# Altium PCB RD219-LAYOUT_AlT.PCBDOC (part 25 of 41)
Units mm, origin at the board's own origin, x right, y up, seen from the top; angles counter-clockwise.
Board outline 209.75 x 159.97 mm, 2 copper layers (TOP, BOTTOM), stack 0 mm thick; 398 components, 199 nets, 1469 pads, 0 vias.
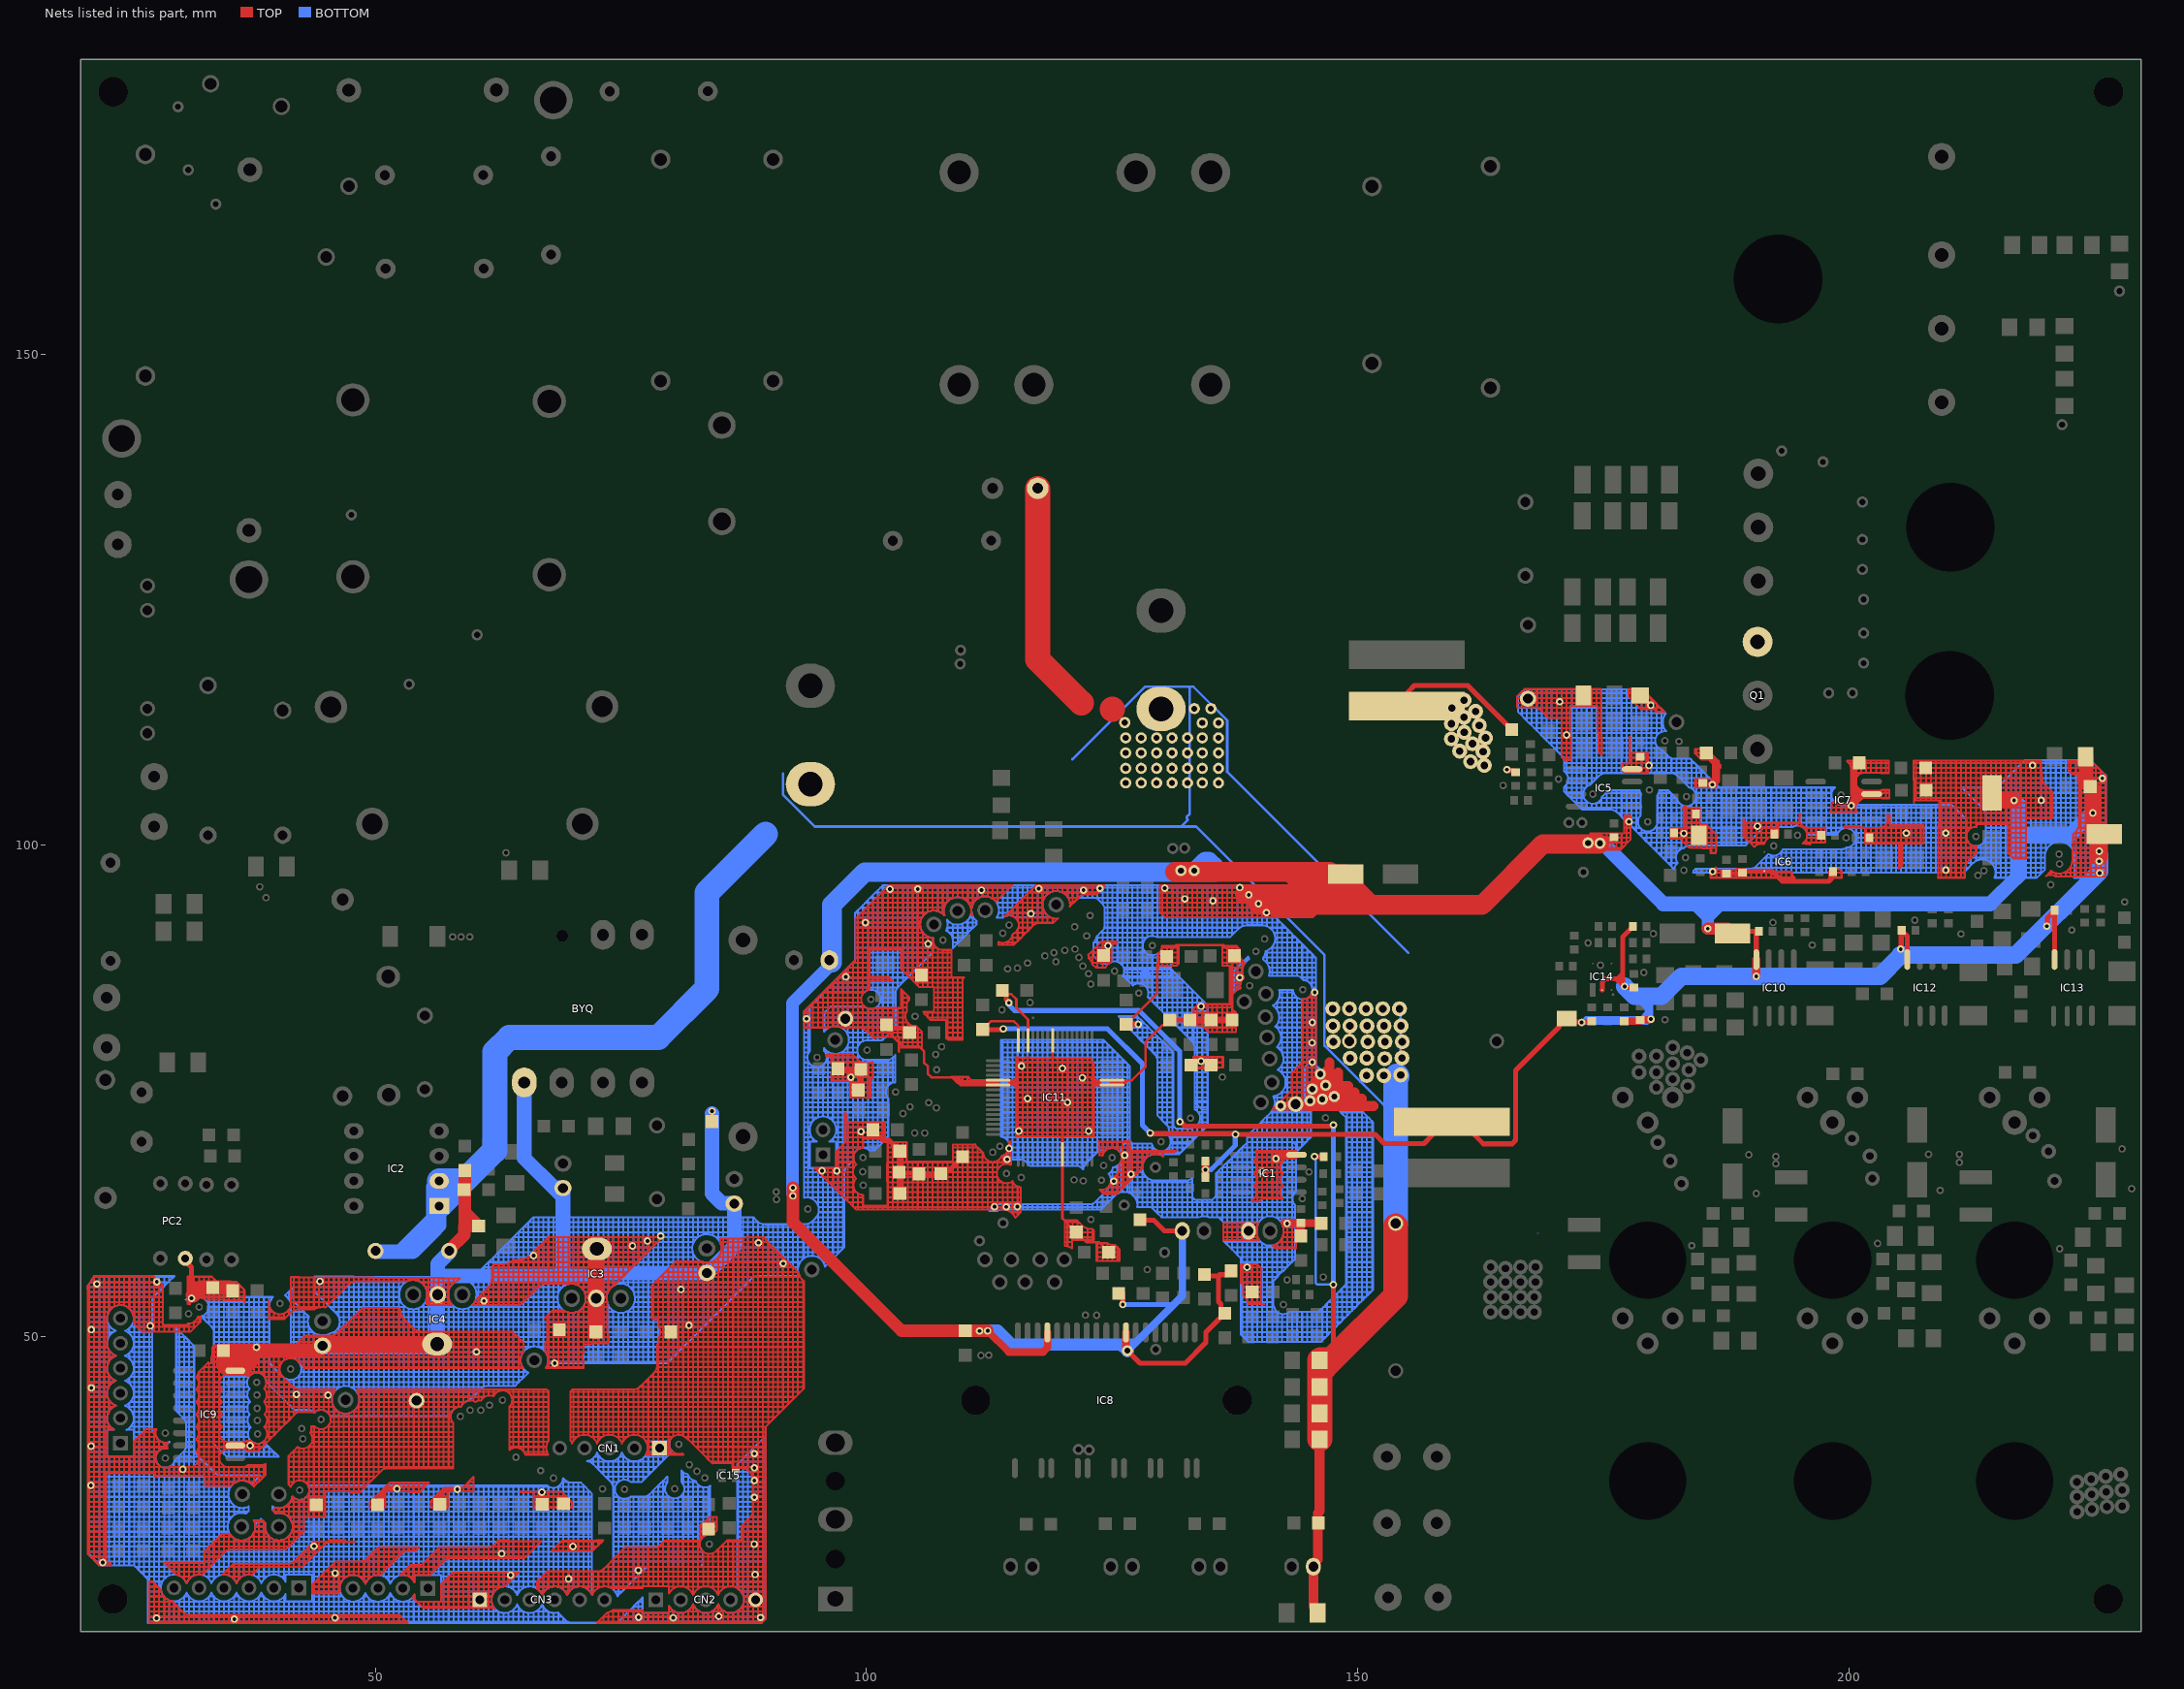
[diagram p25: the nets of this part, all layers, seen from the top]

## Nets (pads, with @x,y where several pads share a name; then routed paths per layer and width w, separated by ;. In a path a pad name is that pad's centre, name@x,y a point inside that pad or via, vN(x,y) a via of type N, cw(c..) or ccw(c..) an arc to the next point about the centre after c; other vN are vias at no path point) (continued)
GND: (continued)
  BOTTOM w0.203: 58.989,20.889 58.989,21.016 ; 58.989,20.889 59.497,20.889 ; 58.989,21.016 58.989,21.524 ; 58.989,21.016 59.497,21.016 ; 58.989,21.524 58.989,22.032 ; 58.989,21.524 59.497,21.524 ; 58.989,22.032 58.989,22.54 ; 58.989,22.032 59.497,22.032 ; 58.989,22.54 58.989,23.048 ; 58.989,22.54 59.497,22.54 ; 58.989,23.048 58.989,23.556 ; 58.989,23.048 59.497,23.048 ; 58.989,23.556 58.989,24.064 ; 58.989,23.556 59.497,23.556 ; 58.989,24.064 58.989,24.572 ; 58.989,24.064 59.497,24.064 ; 58.989,24.572 58.989,25.08 ; 58.989,24.572 59.497,24.572 ; 58.989,25.08 58.989,25.588 ; 58.989,25.08 59.497,25.08 ; 58.989,25.588 58.989,26.096 ; 58.989,25.588 59.497,25.588 ; 58.989,26.096 58.989,26.604 ; 58.989,26.096 59.497,26.096 ; 58.989,26.604 58.989,27.112 ; 58.989,26.604 59.497,26.604 ; 58.989,27.112 58.989,27.62 ; 58.989,27.112 59.497,27.112 ; 58.989,27.62 58.989,28.128 ; 58.989,27.62 59.497,27.62 ; 58.989,28.128 58.989,28.636 ; 58.989,28.128 59.497,28.128 ; 58.989,28.636 58.989,29.144 ; 58.989,28.636 59.497,28.636 ; 58.989,29.144 58.989,29.652 ; 58.989,29.144 59.497,29.144 ; 58.989,29.652 58.989,30.16 ; 58.989,29.652 59.497,29.652 ; 58.989,30.16 58.989,30.668 ; 58.989,30.16 59.497,30.16 ; 58.989,30.668 58.989,31.176 ; 58.989,30.668 59.497,30.668 ; 58.989,31.176 58.989,31.684 ; 58.989,31.176 59.497,31.176 ; 58.989,31.684 58.989,32.192 ; 58.989,31.684 59.497,31.684 ; 58.989,32.192 58.989,32.7 ; 58.989,32.192 59.497,32.192 ; 58.989,32.7 58.989,33.208 ; 58.989,32.7 59.497,32.7 ; 58.989,33.208 58.989,33.716 ; 58.989,33.208 59.497,33.208 ; 58.989,33.716 58.989,34.224 ; 58.989,33.716 59.497,33.716 ; 58.989,34.224 58.989,34.732 ; 58.989,34.224 59.497,34.224 ; 58.989,34.732 58.989,34.866 ; 58.989,34.732 59.497,34.732 ; 58.989,34.866 59.497,34.866 ; 58.989,43.261 cw(c59.646,42.53) 59.133,43.368 ; 58.989,43.261 58.989,43.368 ; 58.989,43.368 58.989,43.876 ; 58.989,43.368 59.133,43.368 ; 58.989,43.876 58.989,44.384 ; 58.989,43.876 59.497,43.876 ; 58.989,44.384 59.497,44.384 ; 58.989,44.384 58.989,44.892 ; 58.989,44.892 59.497,44.892 ; 58.989,44.892 58.989,45.4 ; 58.989,45.4 59.497,45.4 ; 58.989,45.4 58.989,45.908 ; 58.989,45.908 58.989,46.416 ; 58.989,45.908 59.497,45.908 ; 58.989,46.416 59.497,46.416 ; 58.989,46.416 58.989,46.924 ; 58.989,46.924 58.989,47.432 ; 58.989,46.924 59.497,46.924 ; 58.989,47.432 59.497,47.432 ; 58.989,47.432 58.989,47.94 ; 58.989,47.94 58.989,48.448 ; 58.989,47.94 59.497,47.94 ; 58.989,48.448 58.989,48.956 ; 58.989,48.448 59.497,48.448 ; 58.989,48.956 58.989,49.464 ; 58.989,48.956 59.497,48.956 ; 58.989,49.464 58.989,49.972 ; 58.989,49.464 59.497,49.464 ; 58.989,49.972 58.989,50.48 ; 58.989,49.972 59.497,49.972 ; 58.989,50.48 58.989,50.988 ; 58.989,50.48 59.497,50.48 ; 58.989,50.988 59.497,50.988 ; 58.989,50.988 58.989,51.496 ; 58.989,51.496 59.497,51.496 ; 58.989,51.496 58.989,52.004 ; 58.989,52.004 58.989,52.512 ; 58.989,52.004 59.497,52.004 ; 58.989,52.512 59.497,52.512 ; 58.989,52.512 58.989,52.805 ; 58.989,52.805 ccw(c58.862,54.227) 59.497,52.948 ; 58.989,55.775 cw(c58.862,54.354) 59.497,55.632 ; 58.989,55.775 58.989,56.068 ; 58.989,56.068 58.989,56.071 ; 58.989,56.068 59.497,56.068 ; 58.989,56.071 59.497,56.07 ; 59.133,43.368 cw(c59.646,42.53) 59.497,43.501 ; 59.497,20.889 59.497,21.016 ; 59.497,20.889 60.005,20.889 ; 59.497,21.016 59.497,21.524 ; 59.497,21.016 60.005,21.016 ; 59.497,21.524 59.497,22.032 ; 59.497,21.524 60.005,21.524 ; 59.497,22.032 59.497,22.54 ; 59.497,22.032 60.005,22.032 ; 59.497,22.54 59.497,23.048 ; 59.497,22.54 CN3.1@60.005,22.54 ; 59.497,23.048 59.497,23.556 ; 59.497,23.048 CN3.1@60.005,23.048 ; 59.497,23.556 59.497,24.064 ; 59.497,23.556 CN3.1@60.005,23.556 ; 59.497,24.064 59.497,24.572 ; 59.497,24.064 60.005,24.064 ; 59.497,24.572 59.497,25.08 ; 59.497,24.572 60.005,24.572 ; 59.497,25.08 59.497,25.588 ; 59.497,25.08 60.005,25.08 ; 59.497,25.588 59.497,26.096 ; 59.497,25.588 60.005,25.588 ; 59.497,26.096 59.497,26.604 ; 59.497,26.096 60.005,26.096 ; 59.497,26.604 59.497,27.112 ; 59.497,26.604 60.005,26.604 ; 59.497,27.112 59.497,27.62 ; 59.497,27.112 60.005,27.112 ; 59.497,27.62 59.497,28.128 ; 59.497,27.62 60.005,27.62 ; 59.497,28.128 59.497,28.636 ; 59.497,28.128 60.005,28.128 ; 59.497,28.636 59.497,29.144 ; 59.497,28.636 60.005,28.636 ; 59.497,29.144 59.497,29.652 ; 59.497,29.144 60.005,29.144 ; 59.497,29.652 59.497,30.16 ; 59.497,29.652 60.005,29.652 ; 59.497,30.16 59.497,30.668 ; 59.497,30.16 60.005,30.16 ; 59.497,30.668 59.497,31.176 ; 59.497,30.668 60.005,30.668 ; 59.497,31.176 59.497,31.684 ; 59.497,31.176 60.005,31.176 ; 59.497,31.684 59.497,32.192 ; 59.497,31.684 60.005,31.684 ; 59.497,32.192 59.497,32.7 ; 59.497,32.192 60.005,32.192 ; 59.497,32.7 59.497,33.208 ; 59.497,32.7 60.005,32.7 ; 59.497,33.208 59.497,33.716 ; 59.497,33.208 60.005,33.208 ; 59.497,33.716 59.497,34.224 ; 59.497,33.716 60.005,33.716 ; 59.497,34.224 59.497,34.732 ; 59.497,34.224 60.005,34.224 ; 59.497,34.732 59.497,34.866 ; 59.497,34.732 60.005,34.732 ; 59.497,34.866 60.005,34.866 ; 59.497,43.501 59.497,43.876 ; 59.497,43.876 59.497,44.384 ; 59.497,43.876 59.962,43.876 ; 59.497,44.384 59.497,44.892 ; 59.497,44.384 60.005,44.384 ; 59.497,44.892 59.497,45.4 ; 59.497,44.892 60.005,44.892 ; 59.497,45.4 60.005,45.4 ; 59.497,45.4 59.497,45.908 ; 59.497,45.908 59.497,46.416 ; 59.497,45.908 60.005,45.908 ; 59.497,46.416 59.497,46.924 ; 59.497,46.416 60.005,46.416 ; 59.497,46.924 59.497,47.432 ; 59.497,46.924 60.005,46.924 ; 59.497,47.432 59.497,47.94 ; 59.497,47.432 60.005,47.432 ; 59.497,47.94 59.497,48.448 ; 59.497,47.94 60.005,47.94 ; 59.497,48.448 59.497,48.956 ; 59.497,48.448 pad.@60.005,48.448 ; 59.497,48.956 59.497,49.464 ; 59.497,48.956 60.005,48.956 ; 59.497,49.464 59.497,49.972 ; 59.497,49.464 60.005,49.464 ; 59.497,49.972 59.497,50.48 ; 59.497,49.972 60.005,49.972 ; 59.497,50.48 59.497,50.988 ; 59.497,50.48 60.005,50.48 ; 59.497,50.988 59.497,51.496 ; 59.497,50.988 60.005,50.988 ; 59.497,51.496 59.497,52.004 ; 59.497,51.496 60.005,51.496 ; 59.497,52.004 59.497,52.512 ; 59.497,52.004 60.005,52.004 ; 59.497,52.512 60.005,52.512 ; 59.497,52.512 59.497,52.948 ; 59.497,52.948 ccw(c58.862,54.227) 59.624,53.02 ; 59.497,55.632 cw(c58.862,54.354) 59.618,55.564 cw(c58.862,54.354) 59.624,55.56 ; 59.497,55.632 59.497,56.068 ; 59.497,56.068 60.005,56.068 ; 59.497,56.068 59.497,56.07 ; 59.497,56.07 60.005,56.068 ; 59.624,53.02 ccw(c58.862,54.227) 60.002,53.368 ccw(c58.862,54.227) 60.005,53.372 ; 59.624,53.02 60.005,53.02 ; 59.624,55.56 cw(c58.862,54.354) 60.005,55.208 ; 59.624,55.56 60.005,55.56 ; 59.962,43.876 60.005,43.919 ; 60.005,20.889 60.005,21.016 ; 60.005,20.889 60.513,20.889 ; 60.005,21.016 60.005,21.524 ; 60.005,21.016 60.513,21.016 ; 60.005,21.524 60.005,22.032 ; 60.005,21.524 60.513,21.524 ; 60.005,22.032 CN3.1@60.005,22.54 ; 60.005,22.032 60.513,22.032 ; CN3.1@60.005,22.54 CN3.1@60.005,23.048 ; CN3.1@60.005,22.54 CN3.1@60.513,22.54 ; CN3.1@60.005,23.048 CN3.1@60.513,23.048 ; CN3.1@60.005,23.048 CN3.1@60.005,23.556 ; CN3.1@60.005,23.556 60.005,24.064 ; CN3.1@60.005,23.556 CN3.1@60.513,23.556 ; 60.005,24.064 60.005,24.572 ; 60.005,24.064 60.513,24.064 ; 60.005,24.572 60.005,25.08 ; 60.005,24.572 60.513,24.572 ; 60.005,25.08 60.005,25.588 ; 60.005,25.08 60.513,25.08 ; 60.005,25.588 60.005,26.096 ; 60.005,25.588 60.513,25.588 ; 60.005,26.096 60.005,26.604 ; 60.005,26.096 60.513,26.096 ; 60.005,26.604 60.005,27.112 ; 60.005,26.604 60.513,26.604 ; 60.005,27.112 60.005,27.62 ; 60.005,27.112 60.513,27.112 ; 60.005,27.62 60.005,28.128 ; 60.005,27.62 60.513,27.62 ; 60.005,28.128 60.005,28.636 ; 60.005,28.128 60.513,28.128 ; 60.005,28.636 60.005,29.144 ; 60.005,28.636 60.513,28.636 ; 60.005,29.144 60.005,29.652 ; 60.005,29.144 60.513,29.144 ; 60.005,29.652 60.005,30.16 ; 60.005,29.652 60.513,29.652 ; 60.005,30.16 60.005,30.668 ; 60.005,30.16 60.513,30.16 ; 60.005,30.668 60.005,31.176 ; 60.005,30.668 60.513,30.668 ; 60.005,31.176 60.005,31.684 ; 60.005,31.176 60.513,31.176 ; 60.005,31.684 60.005,32.192 ; 60.005,31.684 60.513,31.684 ; 60.005,32.192 60.005,32.7 ; 60.005,32.192 60.513,32.192 ; 60.005,32.7 60.005,33.208 ; 60.005,32.7 60.513,32.7 ; 60.005,33.208 60.005,33.716 ; 60.005,33.208 60.513,33.208 ; 60.005,33.716 60.005,34.224 ; 60.005,33.716 60.513,33.716 ; 60.005,34.224 60.005,34.732 ; 60.005,34.224 60.513,34.224 ; 60.005,34.732 60.005,34.866 ; 60.005,34.732 60.513,34.732 ; 60.005,34.866 60.513,34.866 ; 60.005,43.919 60.47,44.384 ; 60.005,43.919 60.005,44.384 ; 60.005,44.384 60.47,44.384 ; 60.005,44.384 60.005,44.892 ; 60.005,44.892 60.513,44.892 ; 60.005,44.892 60.005,45.4 ; 60.005,45.4 60.513,45.4 ; 60.005,45.4 60.005,45.908 ; 60.005,45.908 60.005,46.416 ; 60.005,45.908 60.513,45.908 ; 60.005,46.416 60.513,46.416 ; 60.005,46.416 60.005,46.924 ; 60.005,46.924 60.005,47.432 ; 60.005,46.924 60.513,46.924 ; 60.005,47.432 60.513,47.432 ; 60.005,47.432 60.005,47.94 ; 60.005,47.94 pad.@60.005,48.448 ; 60.005,47.94 60.513,47.94 ; pad.@60.005,48.448 pad.@60.513,48.448 ; pad.@60.005,48.448 60.005,48.956 ; 60.005,48.956 60.005,49.464 ; 60.005,48.956 60.513,48.956 ; 60.005,49.464 60.005,49.972 ; 60.005,49.464 60.513,49.464 ; 60.005,49.972 60.005,50.48 ; 60.005,49.972 60.513,49.972 ; 60.005,50.48 60.005,50.988 ; 60.005,50.48 60.513,50.48 ; 60.005,50.988 60.513,50.988 ; 60.005,50.988 60.005,51.496 ; 60.005,51.496 60.513,51.496 ; 60.005,51.496 60.005,52.004 ; 60.005,52.004 60.005,52.512 ; 60.005,52.004 60.513,52.004 ; 60.005,52.512 60.005,53.02 ; 60.005,52.512 60.513,52.512 ; 60.005,53.02 60.513,53.02 ; 60.005,53.02 60.005,53.372 ; 60.005,53.372 ccw(c58.862,54.227) 60.106,53.528 ; 60.005,55.208 cw(c58.862,54.354) 60.106,55.052 ; 60.005,55.208 60.005,55.56 ; 60.005,55.56 60.005,56.068 ; 60.005,55.56 60.513,55.56 ; 60.005,56.068 60.132,56.195 60.513,56.576 ; 60.005,56.068 60.513,56.068 ; 60.106,53.528 ccw(c58.862,54.227) 60.276,54.036 ; 60.106,53.528 60.513,53.528 ; 60.106,55.052 cw(c58.862,54.354) 60.276,54.544 ; 60.106,55.052 60.513,55.052 ; 60.276,54.036 ccw(c58.862,54.227) 60.289,54.227 60.289,54.354 ccw(c58.862,54.354) 60.276,54.544 ; 60.276,54.036 60.513,54.036 ; 60.276,54.544 60.513,54.544 ; 60.47,44.384 60.513,44.427 ; 60.513,20.889 60.513,21.016 ; 60.513,20.889 61.021,20.889 ; 60.513,21.016 60.513,21.524 ; 60.513,21.016 61.021,21.016 ; 60.513,21.524 60.513,22.032 ; 60.513,21.524 61.021,21.524 ; 60.513,22.032 CN3.1@60.513,22.54 ; 60.513,22.032 61.021,22.032 ; CN3.1@60.513,22.54 CN3.1@60.513,23.048 ; CN3.1@60.513,22.54 CN3.1@61.021,22.54 ; CN3.1@60.513,23.048 CN3.1@61.021,23.048 ; CN3.1@60.513,23.048 CN3.1@60.513,23.556 ; CN3.1@60.513,23.556 60.513,24.064 ; CN3.1@60.513,23.556 CN3.1@61.021,23.556 ; 60.513,24.064 60.513,24.572 ; 60.513,24.064 61.021,24.064 ; 60.513,24.572 60.513,25.08 ; 60.513,24.572 61.021,24.572 ; 60.513,25.08 60.513,25.588 ; 60.513,25.08 61.021,25.08 ; 60.513,25.588 60.513,26.096 ; 60.513,25.588 61.021,25.588 ; 60.513,26.096 60.513,26.604 ; 60.513,26.096 61.021,26.096 ; 60.513,26.604 60.513,27.112 ; 60.513,26.604 61.021,26.604 ; 60.513,27.112 60.513,27.62 ; 60.513,27.112 61.021,27.112 ; 60.513,27.62 60.513,28.128 ; 60.513,27.62 61.021,27.62 ; 60.513,28.128 60.513,28.636 ; 60.513,28.128 61.021,28.128 ; 60.513,28.636 60.513,29.144 ; 60.513,28.636 61.021,28.636 ; 60.513,29.144 60.513,29.652 ; 60.513,29.144 61.021,29.144 ; 60.513,29.652 60.513,30.16 ; 60.513,29.652 61.021,29.652 ; 60.513,30.16 60.513,30.668 ; 60.513,30.16 61.021,30.16 ; 60.513,30.668 60.513,31.176 ; 60.513,30.668 61.021,30.668 ; 60.513,31.176 60.513,31.684 ; 60.513,31.176 61.021,31.176 ; 60.513,31.684 60.513,32.192 ; 60.513,31.684 61.021,31.684 ; 60.513,32.192 60.513,32.7 ; 60.513,32.192 61.021,32.192 ; 60.513,32.7 60.513,33.208 ; 60.513,32.7 61.021,32.7 ; 60.513,33.208 60.513,33.716 ; 60.513,33.208 61.021,33.208 ; 60.513,33.716 60.513,34.224 ; 60.513,33.716 61.021,33.716 ; 60.513,34.224 60.513,34.732 ; 60.513,34.224 61.021,34.224 ; 60.513,34.732 60.513,34.866 ; 60.513,34.732 61.021,34.732 ; 60.513,34.866 61.021,34.866 ; 60.513,44.427 60.513,44.892 ; 60.513,44.427 60.858,44.772 ; 60.513,44.892 60.513,45.4 ; 60.513,44.892 61.016,44.892 ; 60.513,45.4 61.021,45.4 ; 60.513,45.4 60.513,45.908 ; 60.513,45.908 60.513,46.416 ; 60.513,45.908 61.021,45.908 ; 60.513,46.416 61.021,46.416 ; 60.513,46.416 60.513,46.924 ; 60.513,46.924 60.513,47.432 ; 60.513,46.924 61.021,46.924 ; 60.513,47.432 61.021,47.432 ; 60.513,47.432 60.513,47.94 ; 60.513,47.94 pad.@60.513,48.448 ; 60.513,47.94 61.021,47.94 ; pad.@60.513,48.448 61.021,48.448 ; pad.@60.513,48.448 60.513,48.956 ; 60.513,48.956 60.513,49.464 ; 60.513,48.956 61.021,48.956 ; 60.513,49.464 60.513,49.972 ; 60.513,49.464 61.021,49.464 ; 60.513,49.972 60.513,50.48 ; 60.513,49.972 61.021,49.972 ; 60.513,50.48 60.513,50.988 ; 60.513,50.48 61.021,50.48 ; 60.513,50.988 61.021,50.988 ; 60.513,50.988 60.513,51.496 ; 60.513,51.496 61.021,51.496 ; 60.513,51.496 60.513,52.004 ; 60.513,52.004 60.513,52.512 ; 60.513,52.004 61.021,52.004 ; 60.513,52.512 60.513,53.02 ; 60.513,52.512 61.021,52.512 ; 60.513,53.02 61.021,53.02 ; 60.513,53.02 60.513,53.528 ; 60.513,53.528 60.513,54.036 ; 60.513,53.528 pad.@61.021,53.528 ; 60.513,54.036 60.513,54.544 ; 60.513,54.036 61.021,54.036 ; 60.513,54.544 60.513,55.052 ; 60.513,54.544 61.021,54.544 ; 60.513,55.052 60.513,55.56 ; 60.513,55.052 61.021,55.052 ; 60.513,55.56 60.513,56.068 ; 60.513,55.56 61.021,55.56 ; 60.513,56.068 61.021,56.068 ; 60.513,56.068 60.513,56.195 60.513,56.576 ; 60.513,56.576 61.021,56.576 ; 60.513,56.576 61.021,57.084 ; 60.858,44.772 cw(c61.373,44.257) 61.016,44.892 ; 60.858,44.772 cw(c61.373,44.257) 61.016,44.892 ; 61.016,44.892 cw(c61.373,44.257) 61.021,44.895 ; 61.016,44.892 cw(c61.373,44.257) 61.021,44.895 ; 61.021,20.889 61.021,21.016 ; 61.021,20.889 61.529,20.889 ; 61.021,21.016 61.021,21.524 ; 61.021,21.016 61.529,21.016 ; 61.021,21.524 61.021,22.032 ; 61.021,21.524 61.529,21.524 ; 61.021,22.032 CN3.1@61.021,22.54 ; 61.021,22.032 61.529,22.032 ; CN3.1@61.021,22.54 CN3.1@61.021,23.048 ; CN3.1@61.021,22.54 61.529,22.54 ; CN3.1@61.021,23.048 61.529,23.048 ; CN3.1@61.021,23.048 CN3.1@61.021,23.556 ; CN3.1@61.021,23.556 61.021,24.064 ; CN3.1@61.021,23.556 61.529,23.556 ; 61.021,24.064 61.021,24.572 ; 61.021,24.064 61.529,24.064 ; 61.021,24.572 61.021,25.08 ; 61.021,24.572 61.529,24.572 ; 61.021,25.08 61.021,25.588 ; 61.021,25.08 61.529,25.08 ; 61.021,25.588 61.021,26.096 ; 61.021,25.588 61.529,25.588 ; 61.021,26.096 61.021,26.604 ; 61.021,26.096 61.529,26.096 ; 61.021,26.604 61.021,27.112 ; 61.021,26.604 61.529,26.604 ; 61.021,27.112 61.021,27.62 ; 61.021,27.112 61.529,27.112 ; 61.021,27.62 61.021,28.128 ; 61.021,27.62 61.529,27.62 ; 61.021,28.128 61.021,28.636 ; 61.021,28.128 61.529,28.128 ; 61.021,28.636 61.021,29.144 ; 61.021,28.636 61.529,28.636 ; 61.021,29.144 61.021,29.652 ; 61.021,29.144 61.529,29.144 ; 61.021,29.652 61.021,30.16 ; 61.021,29.652 61.529,29.652 ; 61.021,30.16 61.021,30.668 ; 61.021,30.16 61.529,30.16 ; 61.021,30.668 61.021,31.176 ; 61.021,30.668 61.529,30.668 ; 61.021,31.176 61.021,31.684 ; 61.021,31.176 61.529,31.176 ; 61.021,31.684 61.021,32.192 ; 61.021,31.684 61.529,31.684 ; 61.021,32.192 61.021,32.7 ; 61.021,32.192 61.529,32.192 ; 61.021,32.7 61.021,33.208 ; 61.021,32.7 61.529,32.7 ; 61.021,33.208 61.021,33.716 ; 61.021,33.208 61.529,33.208 ; 61.021,33.716 61.021,34.224 ; 61.021,33.716 61.529,33.716 ; 61.021,34.224 61.021,34.732 ; 61.021,34.224 61.529,34.224 ; 61.021,34.732 61.021,34.866 ; 61.021,34.732 61.529,34.732 ; 61.021,34.866 61.529,34.866 ; 61.021,44.895 cw(c61.373,44.257) 61.373,44.986 ; 61.021,44.895 cw(c61.373,44.257) 61.373,44.986 ; 61.021,44.895 61.021,45.4 ; 61.021,45.4 61.021,45.908 ; 61.021,45.4 61.529,45.4 ; 61.021,45.908 61.021,46.416 ; 61.021,45.908 61.529,45.908 ; 61.021,46.416 61.021,46.924 ; 61.021,46.416 61.529,46.416 ; 61.021,46.924 61.021,47.432 ; 61.021,46.924 61.529,46.924 ; 61.021,47.432 61.021,47.94 ; 61.021,47.432 61.529,47.432 ; 61.021,47.94 61.021,48.448 ; 61.021,47.94 61.529,47.94 ; 61.021,48.448 61.021,48.956 ; 61.021,48.448 61.529,48.448 ; 61.021,48.956 61.021,49.464 ; 61.021,48.956 61.529,48.956 ; 61.021,49.464 61.021,49.972 ; 61.021,49.464 61.529,49.464 ; 61.021,49.972 61.021,50.48 ; 61.021,49.972 61.529,49.972 ; 61.021,50.48 61.021,50.988 ; 61.021,50.48 61.529,50.48 ; 61.021,50.988 61.529,50.988 ; 61.021,50.988 61.021,51.496 ; 61.021,51.496 61.529,51.496 ; 61.021,51.496 61.021,52.004 ; 61.021,52.004 61.021,52.512 ; 61.021,52.004 61.529,52.004 ; 61.021,52.512 61.021,53.02 ; 61.021,52.512 61.529,52.512 ; 61.021,53.02 pad.@61.021,53.528 ; 61.021,53.02 61.529,53.02 ; pad.@61.021,53.528 61.021,54.036 ; pad.@61.021,53.528 61.529,53.528 ; 61.021,54.036 61.021,54.544 ; 61.021,54.036 61.529,54.036 ; 61.021,54.544 61.021,55.052 ; 61.021,54.544 61.529,54.544 ; 61.021,55.052 61.021,55.56 ; 61.021,55.052 61.529,55.052 ; 61.021,55.56 61.021,56.068 ; 61.021,55.56 61.529,55.56 ; 61.021,56.068 61.021,56.195 61.021,56.576 ; 61.021,56.068 61.529,56.068 ; 61.021,56.576 61.529,56.576 ; 61.021,56.576 61.021,57.084 ; 61.021,57.084 61.529,57.084 ; 61.021,57.084 61.529,57.592 ; 61.373,44.986 61.529,44.986 ; 61.529,20.889 61.529,21.016 ; 61.529,20.889 62.037,20.889 ; 61.529,21.016 61.529,21.524 ; 61.529,21.016 62.037,21.016 ; 61.529,21.524 61.529,22.032 ; 61.529,21.524 62.037,21.524 ; 61.529,22.032 61.529,22.54 ; 61.529,22.032 62.037,22.032 ; 61.529,22.54 61.529,23.048 ; 61.529,22.54 62.024,22.54 ; 61.529,23.048 61.529,23.556 ; 61.529,23.048 61.842,23.048 ; 61.529,23.556 61.529,24.064 ; 61.529,23.556 61.866,23.556 ; 61.529,24.064 62.037,24.064 ; 61.529,24.064 61.529,24.572 ; 61.529,24.572 61.529,25.08 ; 61.529,24.572 62.037,24.572 ; 61.529,25.08 61.529,25.588 ; 61.529,25.08 62.037,25.08 ; 61.529,25.588 61.529,26.096 ; 61.529,25.588 62.037,25.588 ; 61.529,26.096 61.529,26.604 ; 61.529,26.096 62.037,26.096 ; 61.529,26.604 61.529,27.112 ; 61.529,26.604 62.037,26.604 ; 61.529,27.112 61.529,27.62 ; 61.529,27.112 62.037,27.112 ; 61.529,27.62 61.529,28.128 ; 61.529,27.62 62.037,27.62 ; 61.529,28.128 61.529,28.636 ; 61.529,28.128 62.037,28.128 ; 61.529,28.636 61.529,29.144 ; 61.529,28.636 62.037,28.636 ; 61.529,29.144 61.529,29.652 ; 61.529,29.144 62.037,29.144 ; 61.529,29.652 61.529,30.16 ; 61.529,29.652 62.037,29.652 ; 61.529,30.16 61.529,30.668 ; 61.529,30.16 62.037,30.16 ; 61.529,30.668 61.529,31.176 ; 61.529,30.668 62.037,30.668 ; 61.529,31.176 61.529,31.684 ; 61.529,31.176 62.037,31.176 ; 61.529,31.684 61.529,32.192 ; 61.529,31.684 62.037,31.684 ; 61.529,32.192 61.529,32.7 ; 61.529,32.192 62.037,32.192 ; 61.529,32.7 61.529,33.208 ; 61.529,32.7 62.037,32.7 ; 61.529,33.208 61.529,33.716 ; 61.529,33.208 62.037,33.208 ; 61.529,33.716 61.529,34.224 ; 61.529,33.716 62.037,33.716 ; 61.529,34.224 61.529,34.732 ; 61.529,34.224 62.037,34.224 ; 61.529,34.732 61.529,34.866 ; 61.529,34.732 62.037,34.732 ; 61.529,34.866 62.037,34.866 ; 61.529,44.986 61.529,45.4 ; 61.529,44.986 62.037,44.986 ; 61.529,45.4 61.529,45.908 ; 61.529,45.4 62.037,45.4 ; 61.529,45.908 61.529,46.416 ; 61.529,45.908 62.037,45.908 ; 61.529,46.416 61.529,46.924 ; 61.529,46.416 62.037,46.416 ; 61.529,46.924 61.529,47.432 ; 61.529,46.924 62.037,46.924 ; 61.529,47.432 61.529,47.94 ; 61.529,47.432 62.037,47.432 ; 61.529,47.94 61.529,48.448 ; 61.529,47.94 62.037,47.94 ; 61.529,48.448 61.529,48.956 ; 61.529,48.448 62.037,48.448 ; 61.529,48.956 61.529,49.464 ; 61.529,48.956 62.037,48.956 ; 61.529,49.464 61.529,49.972 ; 61.529,49.464 62.037,49.464 ; 61.529,49.972 61.529,50.48 ; 61.529,49.972 62.037,49.972 ; 61.529,50.48 61.529,50.988 ; 61.529,50.48 62.037,50.48 ; 61.529,50.988 61.529,51.496 ; 61.529,50.988 62.037,50.988 ; 61.529,51.496 61.529,52.004 ; 61.529,51.496 62.037,51.496 ; 61.529,52.004 61.529,52.512 ; 61.529,52.004 62.037,52.004 ; 61.529,52.512 61.529,53.02 ; 61.529,52.512 62.037,52.512 ; 61.529,53.02 61.529,53.528 ; 61.529,53.02 62.037,53.02 ; 61.529,53.528 62.037,53.528 ; 61.529,53.528 61.529,54.036 ; 61.529,54.036 61.529,54.544 ; 61.529,54.036 62.037,54.036 ; 61.529,54.544 61.529,55.052 ; 61.529,54.544 62.037,54.544 ; 61.529,55.052 61.529,55.56 ; 61.529,55.052 62.037,55.052 ; 61.529,55.56 61.529,56.068 ; 61.529,55.56 62.037,55.56 ; 61.529,56.068 61.529,56.195 61.529,56.576 ; 61.529,56.068 62.037,56.068 ; 61.529,56.576 62.037,56.576 ; 61.529,56.576 61.529,57.084 ; 61.529,57.084 62.037,57.084 ; 61.529,57.084 61.529,57.592 ; 61.529,57.592 62.037,58.1 ; 61.529,57.592 62.037,57.592 ; 61.842,23.048 ccw(c63.18,23.241) 62.024,22.54 ; 61.842,23.048 cw(c63.18,23.241) 61.863,23.545 cw(c63.18,23.241) 61.866,23.556 ; 61.866,23.556 cw(c63.18,23.241) 62.034,23.957 cw(c63.18,23.241) 62.037,23.962 ; 62.024,22.54 ccw(c63.18,23.241) 62.034,22.525 ccw(c63.18,23.241) 62.037,22.52 ; 62.037,20.889 62.037,21.016 ; 62.037,20.889 62.545,20.889 ; 62.037,21.016 62.037,21.524 ; 62.037,21.016 62.545,21.016 ; 62.037,21.524 62.037,22.032 ; 62.037,21.524 62.545,21.524 ; 62.037,22.032 62.545,22.032 ; 62.037,22.032 62.037,22.52 ; 62.037,22.52 ccw(c63.18,23.241) 62.545,22.048 62.545,22.032 ; 62.037,23.962 cw(c63.18,23.241) 62.108,24.064 ; 62.037,23.962 62.037,24.064 ; 62.037,24.064 62.037,24.572 ; 62.037,24.064 62.108,24.064 ; 62.037,24.572 62.037,25.08 ; 62.037,24.572 62.545,24.572 ; 62.037,25.08 62.037,25.588 ; 62.037,25.08 62.545,25.08 ; 62.037,25.588 62.037,26.096 ; 62.037,25.588 62.545,25.588 ; 62.037,26.096 62.037,26.604 ; 62.037,26.096 62.545,26.096 ; 62.037,26.604 62.037,27.112 ; 62.037,26.604 62.545,26.604 ; 62.037,27.112 62.037,27.62 ; 62.037,27.112 62.545,27.112 ; 62.037,27.62 62.037,28.128 ; 62.037,27.62 62.545,27.62 ; 62.037,28.128 62.037,28.636 ; 62.037,28.128 pad.@62.545,28.128 ; 62.037,28.636 62.037,29.144 ; 62.037,28.636 62.545,28.636 ; 62.037,29.144 62.037,29.652 ; 62.037,29.144 62.545,29.144 ; 62.037,29.652 62.037,30.16 ; 62.037,29.652 62.545,29.652 ; 62.037,30.16 62.037,30.668 ; 62.037,30.16 62.545,30.16 ; 62.037,30.668 62.037,31.176 ; 62.037,30.668 62.545,30.668 ; 62.037,31.176 62.037,31.684 ; 62.037,31.176 62.545,31.176 ; 62.037,31.684 62.037,32.192 ; 62.037,31.684 62.545,31.684 ; 62.037,32.192 62.037,32.7 ; 62.037,32.192 62.545,32.192 ; 62.037,32.7 62.037,33.208 ; 62.037,32.7 62.545,32.7 ; 62.037,33.208 62.037,33.716 ; 62.037,33.208 62.545,33.208 ; 62.037,33.716 62.037,34.224 ; 62.037,33.716 62.545,33.716 ; 62.037,34.224 62.037,34.732 ; 62.037,34.224 62.545,34.224 ; 62.037,34.732 62.037,34.866 ; 62.037,34.732 62.545,34.732 ; 62.037,34.866 62.545,34.866 ; 62.037,44.986 62.037,45.4 ; 62.037,44.986 62.545,44.986 ; 62.037,45.4 62.037,45.908 ; 62.037,45.4 62.545,45.4 ; 62.037,45.908 62.037,46.416 ; 62.037,45.908 62.545,45.908 ; 62.037,46.416 62.037,46.924 ; 62.037,46.416 62.545,46.416 ; 62.037,46.924 62.037,47.432 ; 62.037,46.924 62.545,46.924 ; 62.037,47.432 62.037,47.94 ; 62.037,47.432 62.545,47.432 ; 62.037,47.94 62.037,48.448 ; 62.037,47.94 62.545,47.94 ; 62.037,48.448 62.037,48.956 ; 62.037,48.448 62.545,48.448 ; 62.037,48.956 62.037,49.464 ; 62.037,48.956 62.545,48.956 ; 62.037,49.464 62.037,49.972 ; 62.037,49.464 62.545,49.464 ; 62.037,49.972 62.545,49.972 ; 62.037,49.972 62.037,50.48 ; 62.037,50.48 62.037,50.988 ; 62.037,50.48 62.545,50.48 ; 62.037,50.988 62.037,51.496 ; 62.037,50.988 62.545,50.988 ; 62.037,51.496 62.037,52.004 ; 62.037,51.496 62.545,51.496 ; 62.037,52.004 62.037,52.512 ; 62.037,52.004 62.545,52.004 ; 62.037,52.512 62.037,53.02 ; 62.037,52.512 62.545,52.512 ; 62.037,53.02 62.037,53.528 ; 62.037,53.02 62.545,53.02 ; 62.037,53.528 62.037,54.036 ; 62.037,53.528 62.545,53.528 ; 62.037,54.036 62.037,54.544 ; 62.037,54.036 62.545,54.036 ; 62.037,54.544 62.037,55.052 ; 62.037,54.544 62.545,54.544 ; 62.037,55.052 62.037,55.56 ; 62.037,55.052 62.545,55.052 ; 62.037,55.56 62.037,56.068 ; 62.037,55.56 62.545,55.56 ; 62.037,56.068 62.037,56.195 62.037,56.576 ; 62.037,56.068 62.545,56.068 ; 62.037,56.576 62.037,57.084 ; 62.037,56.576 62.545,56.576 ; 62.037,57.084 62.037,57.592 ; 62.037,57.084 62.545,57.084 ; 62.037,57.592 62.037,58.1 ; 62.037,57.592 62.545,57.592 ; 62.037,58.1 62.545,58.608 ; 62.037,58.1 62.545,58.1 ; 62.108,24.064 cw(c63.18,23.241) 62.545,24.434 ; 62.545,20.889 62.545,21.016 ; 62.545,20.889 63.053,20.889 ; 62.545,21.016 62.545,21.524 ; 62.545,21.016 63.053,21.016 ; 62.545,21.524 62.545,22.032 ; 62.545,21.524 63.053,21.524 ; 62.545,22.032 62.576,22.032 ; 62.545,24.434 cw(c63.18,23.241) 62.945,24.572 ; 62.545,24.434 62.545,24.572 ; 62.545,24.572 62.545,25.08 ; 62.545,24.572 62.945,24.572 ; 62.545,25.08 62.545,25.588 ; 62.545,25.08 63.053,25.08 ; 62.545,25.588 62.545,26.096 ; 62.545,25.588 63.053,25.588 ; 62.545,26.096 62.545,26.604 ; 62.545,26.096 63.053,26.096 ; 62.545,26.604 62.545,27.112 ; 62.545,26.604 63.053,26.604 ; 62.545,27.112 62.545,27.62 ; 62.545,27.112 63.053,27.112 ; 62.545,27.62 pad.@62.545,28.128 ; 62.545,27.62 pad.@63.053,27.62 ; pad.@62.545,28.128 62.545,28.636 ; pad.@62.545,28.128 pad.@63.053,28.128 ; 62.545,28.636 62.545,29.144 ; 62.545,28.636 63.053,28.636 ; 62.545,29.144 62.545,29.652 ; 62.545,29.144 63.053,29.144 ; 62.545,29.652 62.545,30.16 ; 62.545,29.652 63.053,29.652 ; 62.545,30.16 62.545,30.668 ; 62.545,30.16 63.053,30.16 ; 62.545,30.668 62.545,31.176 ; 62.545,30.668 63.053,30.668 ; 62.545,31.176 62.545,31.684 ; 62.545,31.176 63.053,31.176 ; 62.545,31.684 62.545,32.192 ; 62.545,31.684 63.053,31.684 ; 62.545,32.192 62.545,32.7 ; 62.545,32.192 63.053,32.192 ; 62.545,32.7 62.545,33.208 ; 62.545,32.7 63.053,32.7 ; 62.545,33.208 62.545,33.716 ; 62.545,33.208 63.053,33.208 ; 62.545,33.716 62.545,34.224 ; 62.545,33.716 63.053,33.716 ; 62.545,34.224 62.545,34.732 ; 62.545,34.224 63.053,34.224 ; 62.545,34.732 62.545,34.866 ; 62.545,34.732 63.053,34.732 ; 62.545,34.866 63.053,34.866 ; 62.545,44.986 62.545,45.4 ; 62.545,44.986 63.053,44.986 ; 62.545,45.4 62.545,45.908 ; 62.545,45.4 63.053,45.4 ; 62.545,45.908 62.545,46.416 ; 62.545,45.908 63.053,45.908 ; 62.545,46.416 62.545,46.924 ; 62.545,46.416 63.053,46.416 ; 62.545,46.924 62.545,47.432 ; 62.545,46.924 63.053,46.924 ; 62.545,47.432 62.545,47.94 ; 62.545,47.432 63.053,47.432 ; 62.545,47.94 62.545,48.448 ; 62.545,47.94 63.053,47.94 ; 62.545,48.448 62.545,48.956 ; 62.545,48.448 63.053,48.448 ; 62.545,48.956 62.545,49.464 ; 62.545,48.956 63.053,48.956 ; 62.545,49.464 62.545,49.972 ; 62.545,49.464 63.053,49.464 ; 62.545,49.972 63.053,49.972 ; 62.545,49.972 62.545,50.48 ; 62.545,50.48 62.545,50.988 ; 62.545,50.48 63.053,50.48 ; 62.545,50.988 62.545,51.496 ; 62.545,50.988 63.053,50.988 ; 62.545,51.496 62.545,52.004 ; 62.545,51.496 63.053,51.496 ; 62.545,52.004 62.545,52.512 ; 62.545,52.004 63.053,52.004 ; 62.545,52.512 62.545,53.02 ; 62.545,52.512 63.053,52.512 ; 62.545,53.02 62.545,53.528 ; 62.545,53.02 63.053,53.02 ; 62.545,53.528 62.545,54.036 ; 62.545,53.528 63.053,53.528 ; 62.545,54.036 62.545,54.544 ; 62.545,54.036 63.053,54.036 ; 62.545,54.544 62.545,55.052 ; 62.545,54.544 63.053,54.544 ; 62.545,55.052 62.545,55.56 ; 62.545,55.052 63.053,55.052 ; 62.545,55.56 62.545,56.068 ; 62.545,55.56 63.053,55.56 ; 62.545,56.068 62.545,56.195 62.545,56.576 ; 62.545,56.068 63.053,56.068 ; 62.545,56.576 62.545,57.084 ; 62.545,56.576 63.053,56.576 ; 62.545,57.084 62.545,57.592 ; 62.545,57.084 63.053,57.084 ; 62.545,57.592 62.545,58.1 ; 62.545,57.592 63.053,57.592 ; 62.545,58.1 62.545,58.608 ; 62.545,58.1 63.053,58.1 ; 62.545,58.608 63.053,59.116 ; 62.545,58.608 63.053,58.608 ; 62.576,22.032 ccw(c63.18,23.241) 63.053,21.895 ; 62.945,24.572 cw(c63.18,23.241) 63.053,24.587 ; 63.053,20.889 63.053,21.016 ; 63.053,20.889 63.561,20.889 ; 63.053,21.016 63.053,21.524 ; 63.053,21.016 63.561,21.016 ; 63.053,21.524 63.561,21.524 ; 63.053,21.524 63.053,21.895 ; 63.053,21.895 ccw(c63.18,23.241) 63.062,21.895 ccw(c63.18,23.241) 63.561,21.944 ; 63.053,24.587 cw(c63.18,23.241) 63.415,24.572 ; 63.053,24.587 63.053,25.08 ; 63.053,25.08 63.053,25.588 ; 63.053,25.08 63.561,25.08 ; 63.053,25.588 63.053,26.096 ; 63.053,25.588 pad.@63.561,25.588 ; 63.053,26.096 63.053,26.604 ; 63.053,26.096 63.561,26.096 ; 63.053,26.604 63.053,27.112 ; 63.053,26.604 63.561,26.604 ; 63.053,27.112 pad.@63.053,27.62 ; 63.053,27.112 63.561,27.112 ; pad.@63.053,27.62 63.561,27.62 ; pad.@63.053,27.62 pad.@63.053,28.128 ; pad.@63.053,28.128 63.053,28.636 ; pad.@63.053,28.128 63.561,28.128 ; 63.053,28.636 63.053,29.144 ; 63.053,28.636 63.561,28.636 ; 63.053,29.144 63.053,29.652 ; 63.053,29.144 63.561,29.144 ; 63.053,29.652 63.053,30.16 ; 63.053,29.652 63.561,29.652 ; 63.053,30.16 63.053,30.668 ; 63.053,30.16 63.561,30.16 ; 63.053,30.668 63.053,31.176 ; 63.053,30.668 63.561,30.668 ; 63.053,31.176 63.053,31.684 ; 63.053,31.176 63.561,31.176 ; 63.053,31.684 63.053,32.192 ; 63.053,31.684 63.561,31.684 ; 63.053,32.192 63.053,32.7 ; 63.053,32.192 63.561,32.192 ; 63.053,32.7 63.053,33.208 ; 63.053,32.7 63.561,32.7 ; 63.053,33.208 63.053,33.716 ; 63.053,33.208 63.561,33.208 ; 63.053,33.716 63.053,34.224 ; 63.053,33.716 63.561,33.716 ; 63.053,34.224 63.053,34.732 ; 63.053,34.224 63.561,34.224 ; 63.053,34.732 63.053,34.866 ; 63.053,34.732 63.561,34.732 ; 63.053,34.866 63.561,34.866 ; 63.053,44.986 63.053,45.4 ; 63.053,44.986 63.561,44.986 ; 63.053,45.4 63.053,45.908 ; 63.053,45.4 63.561,45.4 ; 63.053,45.908 63.053,46.416 ; 63.053,45.908 63.561,45.908 ; 63.053,46.416 63.053,46.924 ; 63.053,46.416 63.561,46.416 ; 63.053,46.924 63.053,47.432 ; 63.053,46.924 63.561,46.924 ; 63.053,47.432 63.053,47.94 ; 63.053,47.432 63.561,47.432 ; 63.053,47.94 63.053,48.448 ; 63.053,47.94 63.561,47.94 ; 63.053,48.448 63.053,48.956 ; 63.053,48.448 63.561,48.448 ; 63.053,48.956 63.053,49.464 ; 63.053,48.956 63.561,48.956 ; 63.053,49.464 63.053,49.972 ; 63.053,49.464 63.561,49.464 ; 63.053,49.972 63.053,50.48 ; 63.053,49.972 63.561,49.972 ; 63.053,50.48 63.053,50.988 ; 63.053,50.48 63.561,50.48 ; 63.053,50.988 63.053,51.496 ; 63.053,50.988 63.561,50.988 ; 63.053,51.496 63.053,52.004 ; 63.053,51.496 63.561,51.496 ; 63.053,52.004 63.053,52.512 ; 63.053,52.004 63.561,52.004 ; 63.053,52.512 63.053,53.02 ; 63.053,52.512 63.561,52.512 ; 63.053,53.02 63.053,53.528 ; 63.053,53.02 63.561,53.02 ; 63.053,53.528 63.053,54.036 ; 63.053,53.528 63.561,53.528 ; 63.053,54.036 63.053,54.544 ; 63.053,54.036 63.561,54.036 ; 63.053,54.544 63.053,55.052 ; 63.053,54.544 63.561,54.544 ; 63.053,55.052 63.053,55.56 ; 63.053,55.052 63.561,55.052 ; 63.053,55.56 63.053,56.068 ; 63.053,55.56 63.561,55.56 ; 63.053,56.068 63.053,56.195 63.053,56.576 ; 63.053,56.068 63.561,56.068 ; 63.053,56.576 63.053,57.084 ; 63.053,56.576 63.561,56.576 ; 63.053,57.084 63.053,57.592 ; 63.053,57.084 63.561,57.084 ; 63.053,57.592 63.053,58.1 ; 63.053,57.592 63.561,57.592 ; 63.053,58.1 63.053,58.608 ; 63.053,58.1 63.561,58.1 ; 63.053,58.608 63.053,59.116 ; 63.053,58.608 63.561,58.608 ; 63.053,59.116 63.561,59.624 ; 63.053,59.116 63.561,59.116 ; 63.415,24.572 cw(c63.18,23.241) 63.553,24.54 cw(c63.18,23.241) 63.561,24.538 ; 63.415,24.572 63.561,24.572 ; 63.561,20.889 63.561,21.016 ; 63.561,20.889 64.069,20.889 ; 63.561,21.016 63.561,21.524 ; 63.561,21.016 64.069,21.016 ; 63.561,21.524 64.069,21.524 ; 63.561,21.524 63.561,21.944 ; 63.561,24.538 cw(c63.18,23.241) 64.067,24.261 cw(c63.18,23.241) 64.069,24.259 ; 63.561,24.538 63.561,24.572 ; 63.561,24.572 63.561,25.08 ; 63.561,24.572 64.069,24.572 ; 63.561,25.08 pad.@63.561,25.588 ; 63.561,25.08 64.069,25.08 ; pad.@63.561,25.588 63.561,26.096 ; pad.@63.561,25.588 pad.@64.069,25.588 ; 63.561,26.096 63.561,26.604 ; 63.561,26.096 64.069,26.096 ; 63.561,26.604 63.561,27.112 ; 63.561,26.604 64.069,26.604 ; 63.561,27.112 63.561,27.62 ; 63.561,27.112 64.069,27.112 ; 63.561,27.62 63.561,28.128 ; 63.561,27.62 64.069,27.62 ; 63.561,28.128 63.561,28.636 ; 63.561,28.128 64.069,28.128 ; 63.561,28.636 63.561,29.144 ; 63.561,28.636 64.069,28.636 ; 63.561,29.144 63.561,29.652 ; 63.561,29.144 64.069,29.144 ; 63.561,29.652 63.561,30.16 ; 63.561,29.652 64.069,29.652 ; 63.561,30.16 63.561,30.668 ; 63.561,30.16 64.069,30.16 ; 63.561,30.668 63.561,31.176 ; 63.561,30.668 64.069,30.668 ; 63.561,31.176 63.561,31.684 ; 63.561,31.176 64.069,31.176 ; 63.561,31.684 63.561,32.192 ; 63.561,31.684 64.069,31.684 ; 63.561,32.192 63.561,32.7 ; 63.561,32.192 64.069,32.192 ; 63.561,32.7 63.561,33.208 ; 63.561,32.7 64.069,32.7 ; 63.561,33.208 63.561,33.716 ; 63.561,33.208 64.069,33.208 ; 63.561,33.716 63.561,34.224 ; 63.561,33.716 64.069,33.716 ; 63.561,34.224 63.561,34.732 ; 63.561,34.224 64.069,34.224 ; 63.561,34.732 63.561,34.866 ; 63.561,34.732 64.069,34.732 ; 63.561,34.866 64.069,34.866 ; 63.561,44.986 64.069,44.986 ; 63.561,44.986 63.561,45.4 ; 63.561,45.4 64.069,45.4 ; 63.561,45.4 63.561,45.908 ; 63.561,45.908 63.561,46.416 ; 63.561,45.908 64.069,45.908 ; 63.561,46.416 64.069,46.416 ; 63.561,46.416 63.561,46.924 ; 63.561,46.924 63.561,47.432 ; 63.561,46.924 64.069,46.924 ; 63.561,47.432 64.069,47.432 ; 63.561,47.432 63.561,47.94 ; 63.561,47.94 63.561,48.448 ; 63.561,47.94 64.069,47.94 ; 63.561,48.448 63.561,48.956 ; 63.561,48.448 64.069,48.448 ; 63.561,48.956 63.561,49.464 ; 63.561,48.956 64.069,48.956 ; 63.561,49.464 63.561,49.972 ; 63.561,49.464 64.069,49.464 ; 63.561,49.972 63.561,50.48 ; 63.561,49.972 64.069,49.972 ; 63.561,50.48 63.561,50.988 ; 63.561,50.48 64.069,50.48 ; 63.561,50.988 64.069,50.988 ; 63.561,50.988 63.561,51.496 ; 63.561,51.496 64.069,51.496 ; 63.561,51.496 63.561,52.004 ; 63.561,52.004 63.561,52.512 ; 63.561,52.004 64.069,52.004 ; 63.561,52.512 63.561,53.02 ; 63.561,52.512 64.069,52.512 ; 63.561,53.02 64.069,53.02 ; 63.561,53.02 63.561,53.528 ; 63.561,53.528 63.561,54.036 ; 63.561,53.528 64.069,53.528 ; 63.561,54.036 64.069,54.036 ; 63.561,54.036 63.561,54.544 ; 63.561,54.544 64.069,54.544 ; 63.561,54.544 63.561,55.052 ; 63.561,55.052 64.069,55.052 ; 63.561,55.052 63.561,55.56 ; 63.561,55.56 63.561,56.068 ; 63.561,55.56 64.069,55.56 ; 63.561,56.068 64.069,56.068 ; 63.561,56.068 63.561,56.195 63.561,56.576 ; 63.561,56.576 64.069,56.576 ; 63.561,56.576 63.561,57.084 ; 63.561,57.084 64.069,57.084 ; 63.561,57.084 63.561,57.592 ; 63.561,57.592 64.069,57.592 ; 63.561,57.592 63.561,58.1 ; 63.561,58.1 63.561,58.608 ; 63.561,58.1 64.069,58.1 ; 63.561,58.608 63.561,59.116 ; 63.561,58.608 64.069,58.608 ; 63.561,59.116 63.561,59.624 ; 63.561,59.116 64.069,59.116 ; 63.561,59.624 64.069,60.132 ; 63.561,59.624 64.069,59.624 ; 64.069,20.889 64.069,21.016 ; 64.069,20.889 64.577,20.889 ; 64.069,21.016 64.069,21.524 ; 64.069,21.016 64.577,21.016 ; 64.069,21.524 64.069,22.032 ; 64.069,21.524 64.577,21.524 ; 64.069,22.032 64.577,22.032 ; 64.069,22.032 64.069,22.223 ; 64.069,22.223 ccw(c63.18,23.241) 64.336,22.54 ; 64.069,24.259 64.069,24.572 ; 64.069,24.572 64.069,25.08 ; 64.069,24.572 64.577,24.572 ; 64.069,25.08 pad.@64.069,25.588 ; 64.069,25.08 64.577,25.08 ; pad.@64.069,25.588 64.577,25.588 ; pad.@64.069,25.588 64.069,26.096 ; 64.069,26.096 64.069,26.604 ; 64.069,26.096 64.577,26.096 ; 64.069,26.604 64.069,27.112 ; 64.069,26.604 64.577,26.604 ; 64.069,27.112 64.069,27.62 ; 64.069,27.112 64.577,27.112 ; 64.069,27.62 64.069,28.128 ; 64.069,27.62 64.577,27.62 ; 64.069,28.128 64.069,28.636 ; 64.069,28.128 64.577,28.128 ; 64.069,28.636 64.069,29.144 ; 64.069,28.636 64.577,28.636 ; 64.069,29.144 64.069,29.652 ; 64.069,29.144 64.577,29.144 ; 64.069,29.652 64.069,30.16 ; 64.069,29.652 64.577,29.652 ; 64.069,30.16 64.069,30.668 ; 64.069,30.16 64.577,30.16 ; 64.069,30.668 64.069,31.176 ; 64.069,30.668 64.577,30.668 ; 64.069,31.176 64.069,31.684 ; 64.069,31.176 64.577,31.176 ; 64.069,31.684 64.069,32.192 ; 64.069,31.684 64.577,31.684 ; 64.069,32.192 64.069,32.7 ; 64.069,32.192 64.577,32.192 ; 64.069,32.7 64.069,33.208 ; 64.069,32.7 64.577,32.7 ; 64.069,33.208 64.069,33.716 ; 64.069,33.208 64.577,33.208 ; 64.069,33.716 64.069,34.224 ; 64.069,33.716 64.577,33.716 ; 64.069,34.224 64.069,34.732 ; 64.069,34.224 64.577,34.224 ; 64.069,34.732 64.069,34.866 ; 64.069,34.732 64.577,34.732 ; 64.069,34.866 64.577,34.866 ; 64.069,44.986 64.069,45.4 ; 64.069,44.986 64.22,44.986 64.577,45.342 ; 64.069,45.4 64.069,45.908 ; 64.069,45.4 64.577,45.4 ; 64.069,45.908 64.069,46.416 ; 64.069,45.908 64.577,45.908 ; 64.069,46.416 64.069,46.924 ; 64.069,46.416 64.577,46.416 ; 64.069,46.924 64.069,47.432 ; 64.069,46.924 64.577,46.924 ; 64.069,47.432 64.069,47.94 ; 64.069,47.432 64.577,47.432 ; 64.069,47.94 64.069,48.448 ; 64.069,47.94 64.577,47.94 ; 64.069,48.448 64.069,48.956 ; 64.069,48.448 64.577,48.448 ; 64.069,48.956 64.069,49.464 ; 64.069,48.956 64.577,48.956 ; 64.069,49.464 64.069,49.972 ; 64.069,49.464 64.577,49.464 ; 64.069,49.972 64.069,50.48 ; 64.069,49.972 64.577,49.972 ; 64.069,50.48 64.069,50.988 ; 64.069,50.48 64.577,50.48 ; 64.069,50.988 64.069,51.496 ; 64.069,50.988 64.577,50.988 ; 64.069,51.496 64.069,52.004 ; 64.069,51.496 64.577,51.496 ; 64.069,52.004 64.069,52.512 ; 64.069,52.004 64.577,52.004 ; 64.069,52.512 64.069,53.02 ; 64.069,52.512 64.577,52.512 ; 64.069,53.02 64.577,53.02 ; 64.069,53.02 64.069,53.528 ; 64.069,53.528 64.069,54.036 ; 64.069,53.528 64.577,53.528 ; 64.069,54.036 64.577,54.036 ; 64.069,54.036 64.069,54.544 ; 64.069,54.544 64.069,55.052 ; 64.069,54.544 64.577,54.544 ; 64.069,55.052 64.069,55.56 ; 64.069,55.052 64.577,55.052 ; 64.069,55.56 64.069,56.068 ; 64.069,55.56 64.577,55.56 ; 64.069,56.068 64.069,56.195 64.069,56.576 ; 64.069,56.068 64.577,56.068 ; 64.069,56.576 64.069,57.084 ; 64.069,56.576 64.577,56.576 ; 64.069,57.084 64.069,57.592 ; 64.069,57.084 64.577,57.084 ; 64.069,57.592 64.069,58.1 ; 64.069,57.592 64.577,57.592 ; 64.069,58.1 64.069,58.608 ; 64.069,58.1 64.577,58.1 ; 64.069,58.608 64.069,59.116 ; 64.069,58.608 64.577,58.608 ; 64.069,59.116 64.069,59.624 ; 64.069,59.116 64.577,59.116 ; 64.069,59.624 64.069,60.132 ; 64.069,59.624 64.577,59.624 ; 64.069,60.132 64.577,60.132 ; 64.069,60.132 64.577,60.64 ; 64.336,22.54 ccw(c63.18,23.241) 64.339,22.545 ccw(c63.18,23.241) 64.45,22.779 ccw(c65.72,23.241) 64.564,22.54 ; 64.336,22.54 64.564,22.54 ; 64.564,22.54 ccw(c65.72,23.241) 64.574,22.525 ccw(c65.72,23.241) 64.577,22.52 ; 64.577,20.889 64.577,21.016 ; 64.577,20.889 65.085,20.889 ; 64.577,21.016 64.577,21.524 ; 64.577,21.016 65.085,21.016 ; 64.577,21.524 64.577,22.032 ; 64.577,21.524 65.085,21.524 ; 64.577,22.032 65.085,22.032 ; 64.577,22.032 64.577,22.52 ; 64.577,22.52 ccw(c65.72,23.241) 65.085,22.048 65.085,22.032 ; 64.577,23.962 cw(c65.72,23.241) 64.648,24.064 ; 64.577,23.962 64.577,24.064 ; 64.577,24.064 64.577,24.572 ; 64.577,24.064 64.648,24.064 ; 64.577,24.572 64.577,25.08 ; 64.577,24.572 65.085,24.572 ; 64.577,25.08 64.577,25.588 ; 64.577,25.08 65.085,25.08 ; 64.577,25.588 64.577,26.096 ; 64.577,25.588 65.085,25.588 ; 64.577,26.096 64.577,26.604 ; 64.577,26.096 65.085,26.096 ; 64.577,26.604 64.577,27.112 ; 64.577,26.604 65.085,26.604 ; 64.577,27.112 64.577,27.62 ; 64.577,27.112 65.085,27.112 ; 64.577,27.62 64.577,28.128 ; 64.577,27.62 65.085,27.62 ; 64.577,28.128 64.577,28.636 ; 64.577,28.128 65.085,28.128 ; 64.577,28.636 64.577,29.144 ; 64.577,28.636 65.085,28.636 ; 64.577,29.144 64.577,29.652 ; 64.577,29.144 65.085,29.144 ; 64.577,29.652 64.577,30.16 ; 64.577,29.652 65.085,29.652 ; 64.577,30.16 64.577,30.668 ; 64.577,30.16 65.085,30.16 ; 64.577,30.668 64.577,31.176 ; 64.577,30.668 65.085,30.668 ; 64.577,31.176 64.577,31.684 ; 64.577,31.176 65.085,31.176 ; 64.577,31.684 64.577,32.192 ; 64.577,31.684 65.085,31.684 ; 64.577,32.192 64.577,32.7 ; 64.577,32.192 65.085,32.192 ; 64.577,32.7 64.577,33.208 ; 64.577,32.7 65.085,32.7 ; 64.577,33.208 64.577,33.716 ; 64.577,33.208 65.085,33.208 ; 64.577,33.716 64.577,34.224 ; 64.577,33.716 65.085,33.716 ; 64.577,34.224 64.577,34.732 ; 64.577,34.224 65.085,34.224 ; 64.577,34.732 64.577,34.866 ; 64.577,34.732 65.085,34.732 ; 64.577,34.866 65.085,34.866 ; 64.577,45.342 64.577,45.4 ; 64.577,45.342 64.635,45.4 ; 64.577,45.4 64.577,45.908 ; 64.577,45.4 64.635,45.4 ; 64.577,45.908 64.577,46.416 ; 64.577,45.908 65.085,45.908 ; 64.577,46.416 64.577,46.924 ; 64.577,46.416 65.085,46.416 ; 64.577,46.924 64.577,47.432 ; 64.577,46.924 64.968,46.924 ; 64.577,47.432 64.577,47.94 ; 64.577,47.432 64.8,47.432 ; 64.577,47.94 64.577,48.448 ; 64.577,47.94 64.828,47.94 ; 64.577,48.448 64.577,48.956 ; 64.577,48.448 65.066,48.448 ; 64.577,48.956 64.577,49.464 ; 64.577,48.956 65.085,48.956 ; 64.577,49.464 64.577,49.972 ; 64.577,49.464 65.085,49.464 ; 64.577,49.972 64.577,50.48 ; 64.577,49.972 65.085,49.972 ; 64.577,50.48 64.577,50.988 ; 64.577,50.48 65.085,50.48 ; 64.577,50.988 65.085,50.988 ; 64.577,50.988 64.577,51.496 ; 64.577,51.496 65.085,51.496 ; 64.577,51.496 64.577,52.004 ; 64.577,52.004 64.577,52.512 ; 64.577,52.004 65.085,52.004 ; 64.577,52.512 64.577,53.02 ; 64.577,52.512 65.085,52.512 ; 64.577,53.02 65.085,53.02 ; 64.577,53.02 64.577,53.528 ; 64.577,53.528 64.577,54.036 ; 64.577,53.528 65.085,53.528 ; 64.577,54.036 65.085,54.036 ; 64.577,54.036 64.577,54.544 ; 64.577,54.544 64.577,55.052 ; 64.577,54.544 65.085,54.544 ; 64.577,55.052 64.577,55.56 ; 64.577,55.052 65.085,55.052 ; 64.577,55.56 64.577,56.068 ; 64.577,55.56 65.085,55.56 ; 64.577,56.068 64.577,56.195 64.577,56.576 ; 64.577,56.068 65.085,56.068 ; 64.577,56.576 64.577,57.084 ; 64.577,56.576 65.085,56.576 ; 64.577,57.084 64.577,57.592 ; 64.577,57.084 65.085,57.084 ; 64.577,57.592 64.577,58.1 ; 64.577,57.592 65.085,57.592 ; 64.577,58.1 64.577,58.608 ; 64.577,58.1 65.085,58.1 ; 64.577,58.608 64.577,59.116 ; 64.577,58.608 65.085,58.608 ; 64.577,59.116 64.577,59.624 ; 64.577,59.116 65.085,59.116 ; 64.577,59.624 64.577,60.132 ; 64.577,59.624 65.085,59.624 ; 64.577,60.132 65.085,60.132 ; 64.577,60.132 64.577,60.64 ; 64.577,60.64 65.085,61.148 ; 64.577,60.64 65.085,60.64 ; 64.635,45.4 65.085,45.85 ; 64.648,24.064 cw(c65.72,23.241) 65.085,24.434 ; 64.8,47.432 ccw(c66.19,47.61) 64.964,46.931 ccw(c66.19,47.61) 64.968,46.924 ; 64.8,47.432 cw(c66.19,47.61) 64.828,47.94 ; 64.828,47.94 cw(c66.19,47.61) 64.83,47.949 cw(c66.19,47.61) 65.066,48.448 ; 64.968,46.924 ccw(c66.19,47.61) 65.085,46.748 65.085,46.416 ; 65.066,48.448 cw(c66.19,47.61) 65.085,48.473 65.085,48.956 ; 65.085,20.889 65.085,21.016 ; 65.085,20.889 65.593,20.889 ; 65.085,21.016 65.085,21.524 ; 65.085,21.016 65.593,21.016 ; 65.085,21.524 65.085,22.032 ; 65.085,21.524 65.593,21.524 ; 65.085,22.032 65.116,22.032 ; 65.085,24.434 cw(c65.72,23.241) 65.485,24.572 ; 65.085,24.434 65.085,24.572 ; 65.085,24.572 65.085,25.08 ; 65.085,24.572 65.485,24.572 ; 65.085,25.08 65.085,25.588 ; 65.085,25.08 65.593,25.08 ; 65.085,25.588 65.085,26.096 ; 65.085,25.588 65.593,25.588 ; 65.085,26.096 65.085,26.604 ; 65.085,26.096 65.593,26.096 ; 65.085,26.604 65.085,27.112 ; 65.085,26.604 65.593,26.604 ; 65.085,27.112 65.085,27.62 ; 65.085,27.112 65.593,27.112 ; 65.085,27.62 65.085,28.128 ; 65.085,27.62 65.593,27.62 ; 65.085,28.128 65.085,28.636 ; 65.085,28.128 65.593,28.128 ; 65.085,28.636 65.085,29.144 ; 65.085,28.636 65.593,28.636 ; 65.085,29.144 65.085,29.652 ; 65.085,29.144 65.593,29.144 ; 65.085,29.652 65.085,30.16 ; 65.085,29.652 65.593,29.652 ; 65.085,30.16 65.085,30.668 ; 65.085,30.16 65.593,30.16 ; 65.085,30.668 65.085,31.176 ; 65.085,30.668 65.593,30.668 ; 65.085,31.176 65.085,31.684 ; 65.085,31.176 65.593,31.176 ; 65.085,31.684 65.085,32.192 ; 65.085,31.684 65.593,31.684 ; 65.085,32.192 65.085,32.7 ; 65.085,32.192 65.593,32.192 ; 65.085,32.7 65.085,33.208 ; 65.085,32.7 65.593,32.7 ; 65.085,33.208 65.085,33.716 ; 65.085,33.208 65.593,33.208 ; 65.085,33.716 65.085,34.224 ; 65.085,33.716 65.593,33.716 ; 65.085,34.224 65.085,34.732 ; 65.085,34.224 65.593,34.224 ; 65.085,34.732 65.085,34.866 ; 65.085,34.732 65.593,34.732 ; 65.085,34.866 65.593,34.866 ; 65.085,45.85 65.085,45.908 ; 65.085,45.85 65.143,45.908 ; 65.085,45.908 65.085,46.416 ; 65.085,45.908 65.143,45.908 ; 65.085,46.416 65.457,46.416 ; 65.085,48.956 65.085,49.464 ; 65.085,48.956 65.593,48.956 ; 65.085,49.464 65.085,49.972 ; 65.085,49.464 65.593,49.464 ; 65.085,49.972 65.085,50.48 ; 65.085,49.972 65.593,49.972 ; 65.085,50.48 65.085,50.988 ; 65.085,50.48 65.593,50.48 ; 65.085,50.988 65.593,50.988 ; 65.085,50.988 65.085,51.496 ; 65.085,51.496 65.593,51.496 ; 65.085,51.496 65.085,52.004 ; 65.085,52.004 65.085,52.512 ; 65.085,52.004 65.593,52.004 ; 65.085,52.512 65.085,53.02 ; 65.085,52.512 65.593,52.512 ; 65.085,53.02 65.593,53.02 ; 65.085,53.02 65.085,53.528 ; 65.085,53.528 65.085,54.036 ; 65.085,53.528 65.593,53.528 ; 65.085,54.036 65.593,54.036 ; 65.085,54.036 65.085,54.544 ; 65.085,54.544 65.593,54.544 ; 65.085,54.544 65.085,55.052 ; 65.085,55.052 65.593,55.052 ; 65.085,55.052 65.085,55.56 ; 65.085,55.56 65.085,56.068 ; 65.085,55.56 65.593,55.56 ; 65.085,56.068 65.593,56.068 ; 65.085,56.068 65.085,56.195 65.085,56.576 ; 65.085,56.576 65.593,56.576 ; 65.085,56.576 65.085,57.084 ; 65.085,57.084 65.593,57.084 ; 65.085,57.084 65.085,57.592 ; 65.085,57.592 65.593,57.592 ; 65.085,57.592 65.085,58.1 ; 65.085,58.1 65.085,58.608 ; 65.085,58.1 65.593,58.1 ; 65.085,58.608 65.085,59.116 ; 65.085,58.608 65.593,58.608 ; 65.085,59.116 65.085,59.624 ; 65.085,59.116 65.593,59.116 ; 65.085,59.624 65.085,60.132 ; 65.085,59.624 65.593,59.624 ; 65.085,60.132 65.593,60.132 ; 65.085,60.132 65.085,60.64 ; 65.085,60.64 65.593,60.64 ; 65.085,60.64 65.085,61.148 ; 65.085,61.148 65.593,61.656 ; 65.085,61.148 65.593,61.148 ; 65.116,22.032 ccw(c65.72,23.241) 65.593,21.895 ; 65.485,24.572 cw(c65.72,23.241) 65.593,24.587 ; 65.593,20.889 65.593,21.016 ; 65.593,20.889 66.101,20.889 ; 65.593,21.016 65.593,21.524 ; 65.593,21.016 66.101,21.016 ; 65.593,21.524 66.101,21.524 ; 65.593,21.524 65.593,21.895 ; 65.593,21.895 ccw(c65.72,23.241) 65.602,21.895 ccw(c65.72,23.241) 66.101,21.944 ; 65.593,24.587 cw(c65.72,23.241) 65.955,24.572 ; 65.593,24.587 65.593,25.08 ; 65.593,25.08 65.593,25.588 ; 65.593,25.08 66.101,25.08 ; 65.593,25.588 65.593,26.096 ; 65.593,25.588 66.101,25.588 ; 65.593,26.096 65.593,26.604 ; 65.593,26.096 66.101,26.096 ; 65.593,26.604 65.593,27.112 ; 65.593,26.604 66.101,26.604 ; 65.593,27.112 65.593,27.62 ; 65.593,27.112 66.101,27.112 ; 65.593,27.62 65.593,28.128 ; 65.593,27.62 66.101,27.62 ; 65.593,28.128 65.593,28.636 ; 65.593,28.128 66.101,28.128 ; 65.593,28.636 65.593,29.144 ; 65.593,28.636 66.101,28.636 ; 65.593,29.144 65.593,29.652 ; 65.593,29.144 66.101,29.144 ; 65.593,29.652 65.593,30.16 ; 65.593,29.652 66.101,29.652 ; 65.593,30.16 65.593,30.668 ; 65.593,30.16 66.101,30.16 ; 65.593,30.668 65.593,31.176 ; 65.593,30.668 66.101,30.668 ; 65.593,31.176 65.593,31.684 ; 65.593,31.176 66.101,31.176 ; 65.593,31.684 65.593,32.192 ; 65.593,31.684 66.101,31.684 ; 65.593,32.192 65.593,32.7 ; 65.593,32.192 66.101,32.192 ; 65.593,32.7 65.593,33.208 ; 65.593,32.7 66.101,32.7 ; 65.593,33.208 65.593,33.716 ; 65.593,33.208 66.101,33.208 ; 65.593,33.716 65.593,34.224 ; 65.593,33.716 66.101,33.716 ; 65.593,34.224 65.593,34.732 ; 65.593,34.224 66.101,34.224 ; 65.593,34.732 65.593,34.866 ; 65.593,34.732 66.101,34.732 ; 65.593,34.866 66.101,34.866 ; 65.593,48.878 cw(c66.19,47.61) 65.798,48.956 ; 65.593,48.878 65.593,48.956 ; 65.593,48.956 65.593,49.464 ; 65.593,48.956 65.798,48.956 ; 65.593,49.464 65.593,49.972 ; 65.593,49.464 66.101,49.464 ; 65.593,49.972 65.593,50.48 ; 65.593,49.972 66.101,49.972 ; 65.593,50.48 65.593,50.988 ; 65.593,50.48 66.101,50.48 ; 65.593,50.988 65.593,51.496 ; 65.593,50.988 66.101,50.988 ; 65.593,51.496 65.593,52.004 ; 65.593,51.496 66.101,51.496 ; 65.593,52.004 65.593,52.512 ; 65.593,52.004 66.101,52.004 ; 65.593,52.512 65.593,53.02 ; 65.593,52.512 66.101,52.512 ; 65.593,53.02 66.101,53.02 ; 65.593,53.02 65.593,53.528 ; 65.593,53.528 65.593,54.036 ; 65.593,53.528 66.101,53.528 ; 65.593,54.036 65.593,54.544 ; 65.593,54.036 66.101,54.036 ; 65.593,54.544 65.593,55.052 ; 65.593,54.544 66.101,54.544 ; 65.593,55.052 66.101,55.052 ; 65.593,55.052 65.593,55.56 ; 65.593,55.56 65.593,56.068 ; 65.593,55.56 66.101,55.56 ; 65.593,56.068 66.101,56.068 ; 65.593,56.068 65.593,56.195 65.593,56.576 ; 65.593,56.576 65.593,57.084 ; 65.593,56.576 66.101,56.576 ; 65.593,57.084 65.593,57.592 ; 65.593,57.084 66.101,57.084 ; 65.593,57.592 66.101,57.592 ; 65.593,57.592 65.593,58.1 ; 65.593,58.1 65.593,58.608 ; 65.593,58.1 pad.@66.101,58.1 ; 65.593,58.608 65.593,59.116 ; 65.593,58.608 pad.@66.101,58.608 ; 65.593,59.116 65.593,59.624 ; 65.593,59.116 66.101,59.116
